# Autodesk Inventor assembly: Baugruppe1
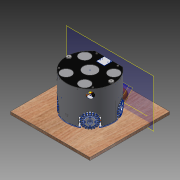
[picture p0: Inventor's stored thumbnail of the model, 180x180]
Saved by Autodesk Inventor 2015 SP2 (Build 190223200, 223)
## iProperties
Created: 2012-07
Part Number: Baugruppe1
Document SubType Name: Assembly
Designer: rYan
Author: rYan
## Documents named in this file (4)
- D:\TIGERs GIT\Hardware\mechanik\2016\Inventor\Demo mit Boden.iam
- D:\TIGERs GIT\Hardware\mechanik\2016\Inventor\Boden.ipt
- D:\TIGERs GIT\Hardware\mechanik\2016\Inventor\HBG-Roboter.iam
- D:\TIGERs GIT\Hardware\mechanik\2016\Inventor\Golfball.ipt
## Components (3 placed, 3 different names)
1. Boden:1 — Passend:3, Passend:4, Passend:5, Passend:6, Winkel:1, Tangential:1, Winkel:3, Winkel:4, Fluchtend:2, Fluchtend:3, Passend:13
2. HBG-Roboter:1 [sub-assembly] — Winkel:3, Tangential:2, Tangential:3, Fluchtend:2, Fluchtend:3, Tangential:4, Passend:11, Passend:12, Passend:13, Winkel:5, Winkel:6
3. Golfball:1 — Tangential:1, Tangential:3, Tangential:4, Winkel:5, Winkel:6
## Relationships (18: Mate 7, Angle 5, Tangent 4, Flush 2)
- Passend:3 [Mate]: Boden:1
- Passend:4 [Mate]: Boden:1
- Passend:5 [Mate]: Boden:1
- Passend:6 [Mate]: Boden:1
- Winkel:1 [Angle]: Boden:1
- Tangential:1: Boden:1 ↔ Golfball:1
- Winkel:3 [Angle]: Boden:1 ↔ HBG-Roboter:1
- Winkel:4 [Angle]: Boden:1
- Tangential:2: HBG-Roboter:1
- Tangential:3: HBG-Roboter:1 ↔ Golfball:1
- Fluchtend:2 [Flush]: Boden:1 ↔ HBG-Roboter:1
- Fluchtend:3 [Flush]: Boden:1 ↔ HBG-Roboter:1
- Tangential:4: HBG-Roboter:1 ↔ Golfball:1
- Passend:11 [Mate]: HBG-Roboter:1
- Passend:12 [Mate]: HBG-Roboter:1
- Passend:13 [Mate]: Boden:1 ↔ HBG-Roboter:1
- Winkel:5 [Angle]: HBG-Roboter:1 ↔ Golfball:1
- Winkel:6 [Angle]: HBG-Roboter:1 ↔ Golfball:1
